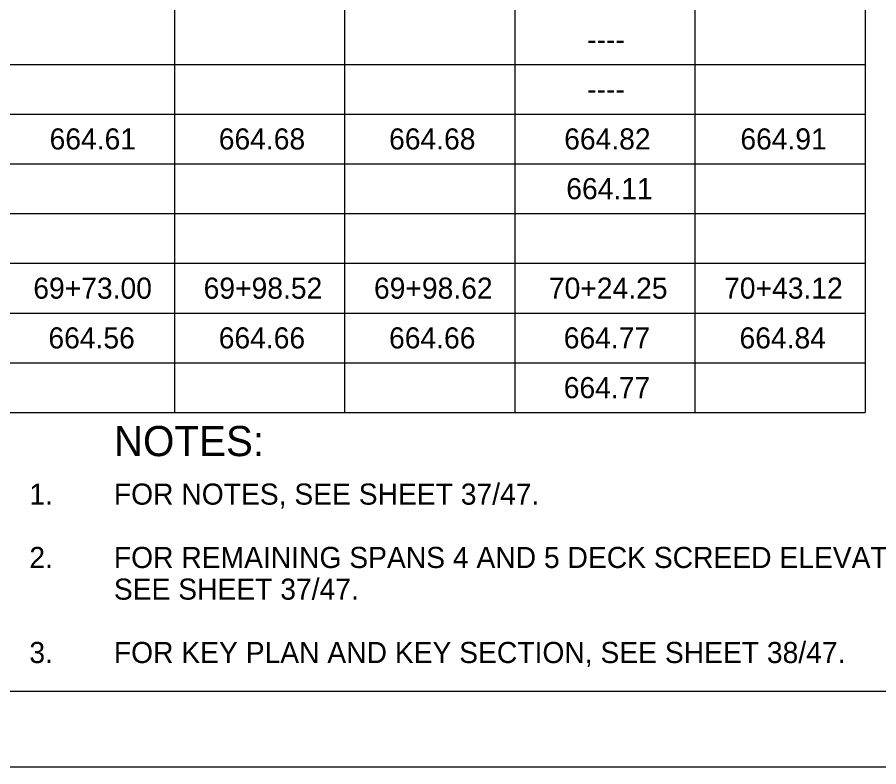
# Model space of a CAD drawing. Extents: x 0 to 34, y 0 to 22.
# Drawn here: x 24.95 to 30.66, y 0 to 4.97 of the extents above; entities that cross this region are included whole.
import ezdxf

# ---------------------------------------------------------------- set-up
doc = ezdxf.new("R2010")
doc.units = 0
for name, color, linetype in [('BR_P_Gen_Text', 7, 'Continuous'), ('SH_Border', 7, 'Continuous'), ('SH_Cut_Line', 7, 'Continuous'), ('SH_Text', 7, 'Continuous')]:
    doc.layers.add(name, color=color, linetype=linetype)

msp = doc.modelspace()

# ---------------------------------------------------------------- linework, layer by layer
at = {"layer": 'SH_Border'}
msp.add_lwpolyline([(1.5, 21.5), (33.5, 21.5), (33.5, 0.5), (1.5, 0.5)], close=True, dxfattribs=at)
at = {"layer": 'SH_Cut_Line'}
msp.add_lwpolyline([(0, 0), (34, 0), (34, 22), (0, 22)], close=True, dxfattribs=at)
at = {"layer": 'SH_Text'}
for p, q in [((30.5716, 21.1802), (30.5716, 2.3487)), ((25.9937, 20.0008), (25.9937, 2.3487)), ((27.1223, 20.0008), (27.1223, 2.3487)), ((28.2509, 20.0008), (28.2509, 2.3487)), ((29.4429, 20.0008), (29.4429, 2.3487)), ((4.1947, 4.6566), (30.5716, 4.6566)), ((4.1947, 4.3269), (30.5716, 4.3269)), ((4.1947, 3.9972), (30.5716, 3.9972)), ((2.7998, 3.6675), (30.5716, 3.6675)), ((2.7998, 3.3378), (30.5716, 3.3378)), ((4.1947, 3.0081), (30.5716, 3.0081)), ((4.1947, 2.6784), (30.5716, 2.6784)), ((2.7998, 2.3487), (30.5716, 2.3487))]:
    msp.add_line(p, q, dxfattribs=at)

# ---------------------------------------------------------------- texts
at = {"layer": 'BR_P_Gen_Text'}
for s, height, p in [('NOTES:', 0.2, (25.5929, 2.0593)), ('FOR NOTES, SEE SHEET 37/47.', 0.14, (25.5929, 1.7376)), ('1.   ', 0.14, (25.0329, 1.7376)), ('2.   ', 0.14, (25.0329, 1.3176)), ('FOR REMAINING SPANS 4 AND 5 DECK SCREED ELEVATIONS,', 0.14, (25.5929, 1.3176)), ('SEE SHEET 37/47.', 0.14, (25.5929, 1.1076)), ('3.', 0.14, (25.0329, 0.6876)), ('FOR KEY PLAN AND KEY SECTION, SEE SHEET 38/47.', 0.14, (25.5929, 0.6876))]:
    msp.add_text(s, height=height, dxfattribs=at).set_placement(p)
at = {"layer": 'SH_Text'}
for s, p in [('----', (28.7296, 4.7515)), ('----', (28.7296, 4.4218)), ('664.61', (25.167, 4.0921)), ('664.68', (26.2881, 4.0921)), ('664.68', (27.4168, 4.0921)), ('664.82', (28.5773, 4.0921)), ('664.91', (29.7449, 4.0921)), ('664.11', (28.5911, 3.7624)), ('69+73.00', (25.0591, 3.1029)), ('69+98.52', (26.188, 3.1029)), ('69+98.62', (27.3167, 3.1029)), ('70+24.25', (28.4761, 3.1029)), ('70+43.12', (29.6373, 3.1029)), ('664.56', (25.1592, 2.7732)), ('664.66', (26.2879, 2.7732)), ('664.66', (27.4165, 2.7732)), ('664.77', (28.5744, 2.7732)), ('664.84', (29.7392, 2.7732)), ('664.77', (28.5744, 2.4435))]:
    msp.add_text(s, height=0.14, dxfattribs=at).set_placement(p)

doc.saveas('drawing.dxf')
